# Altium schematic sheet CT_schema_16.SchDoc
size 389 x 385 mm
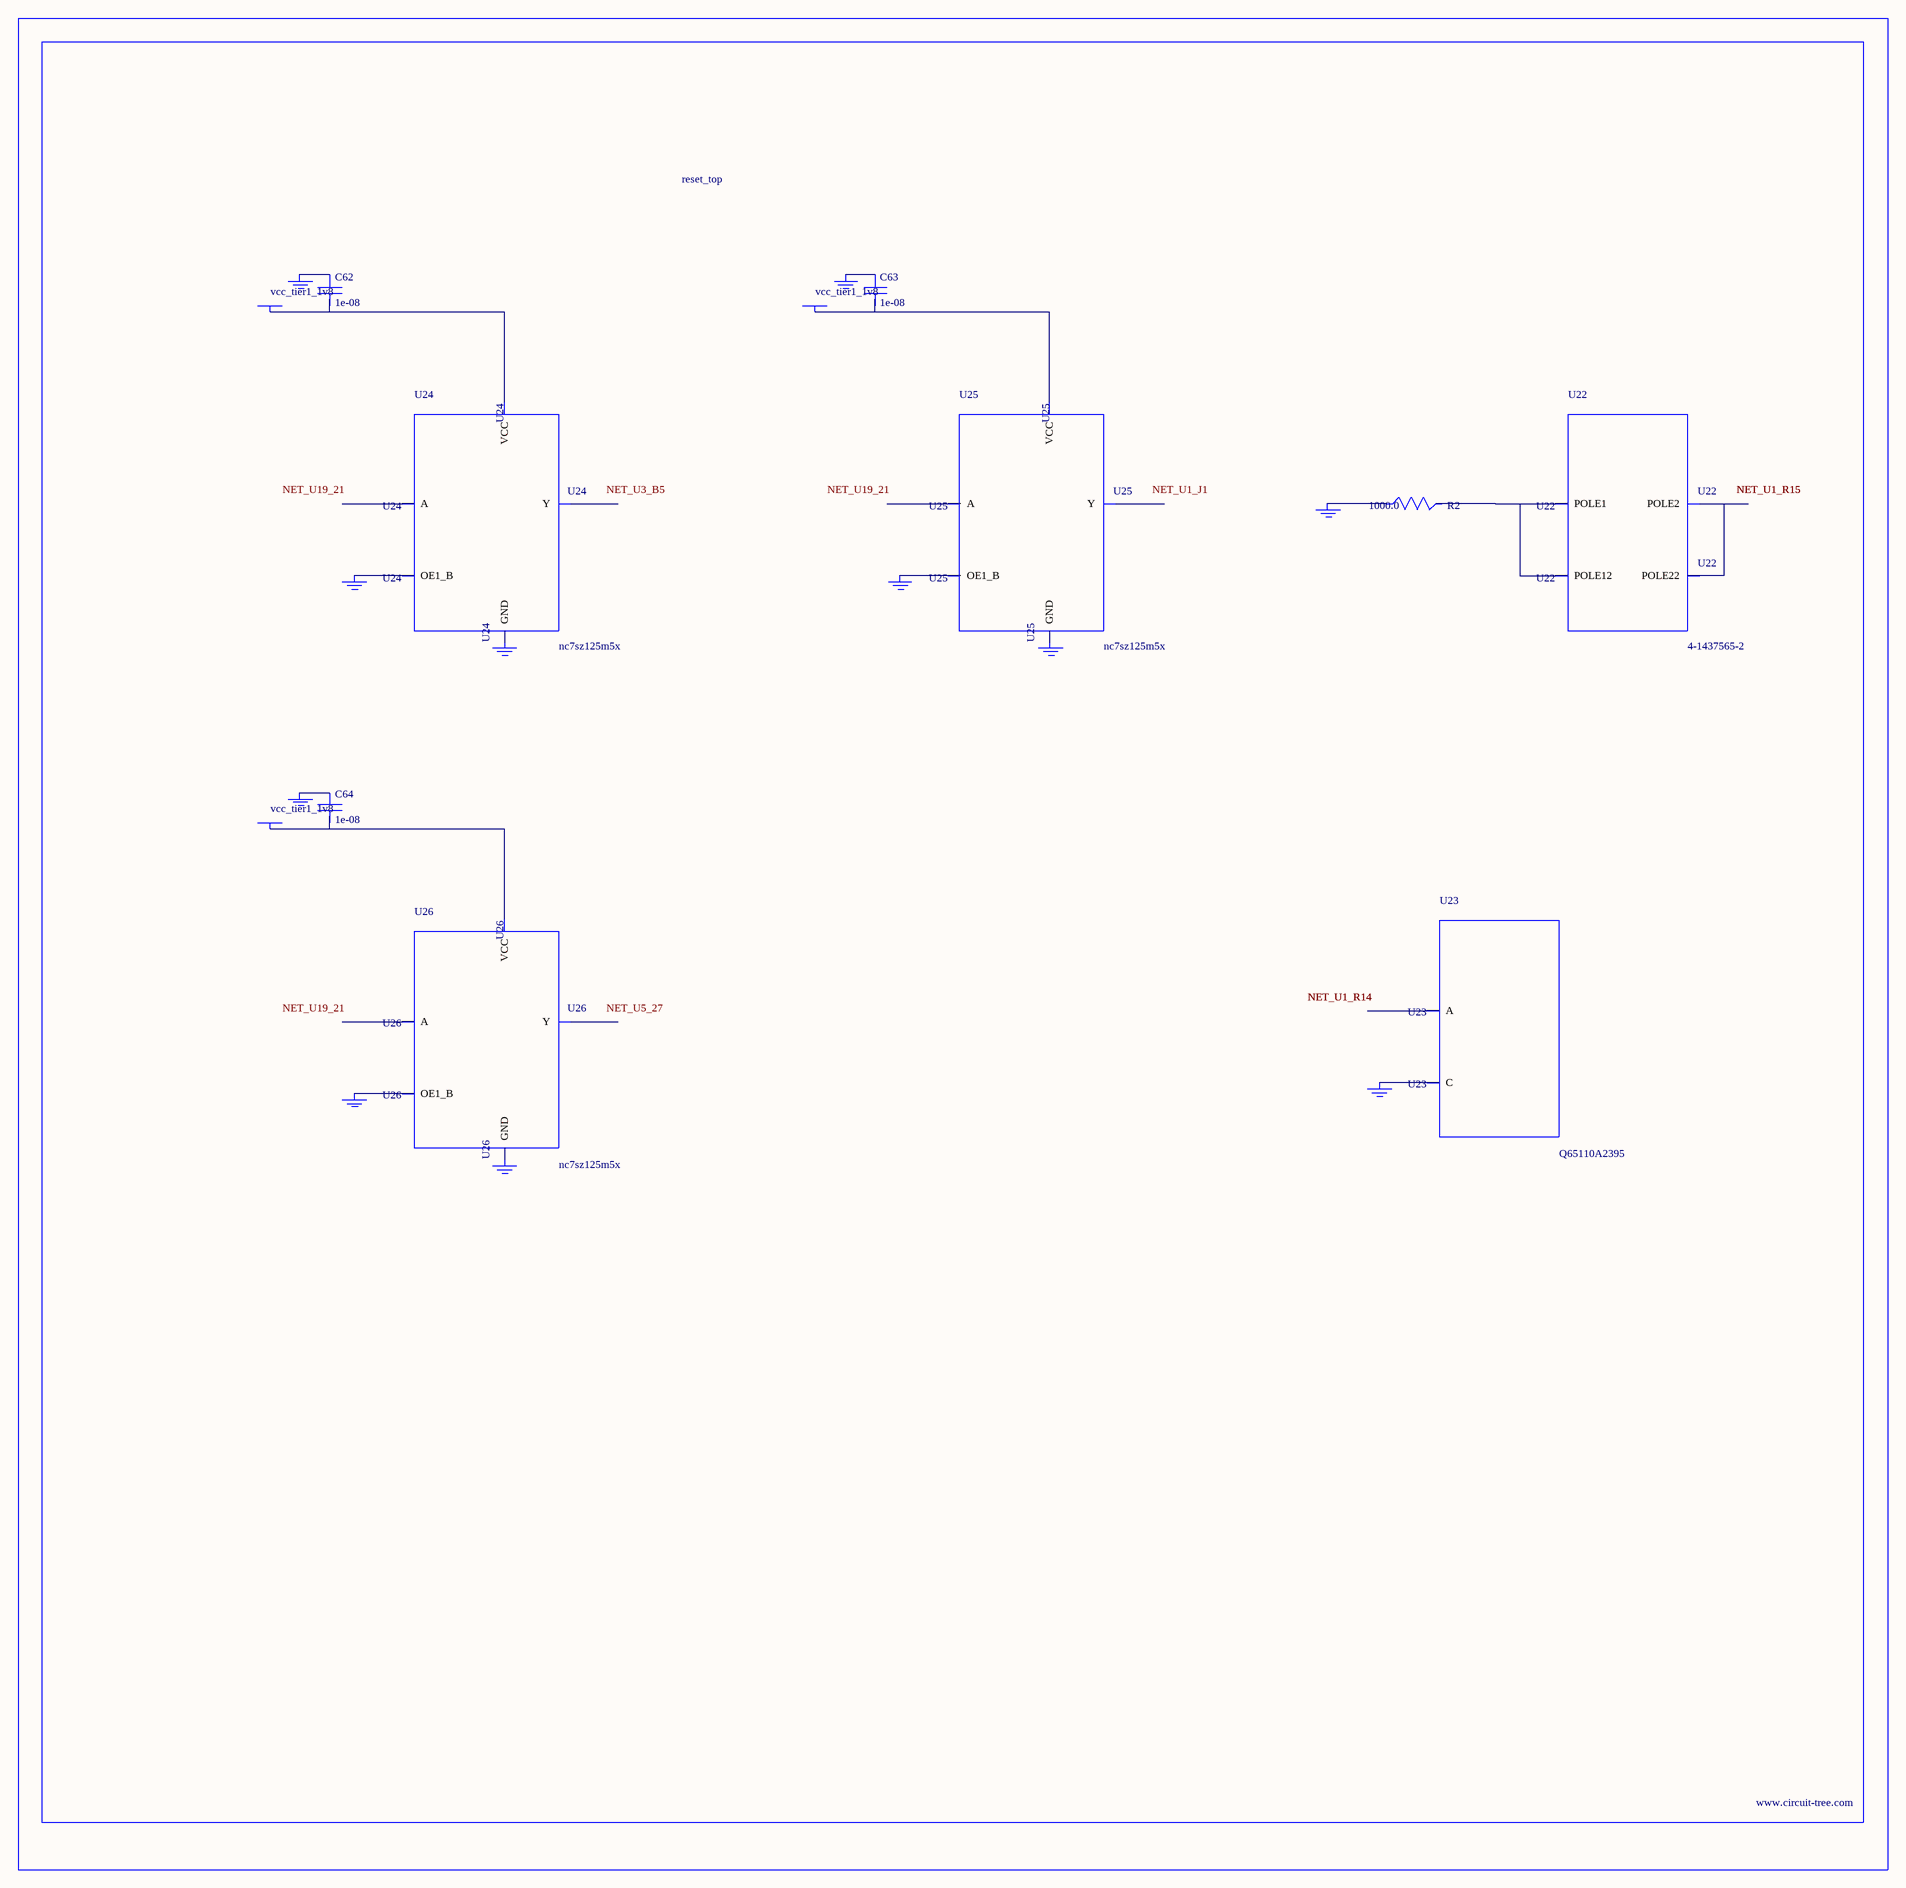
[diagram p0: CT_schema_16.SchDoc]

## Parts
BORDER15  (no value)
C62  1e-08  [C0402]
C63  1e-08  [C0402]
C64  1e-08  [C0402]
GND_INSTANCE_15_0  (no value)
GND_INSTANCE_15_1  (no value)
GND_INSTANCE_15_2  (no value)
GND_INSTANCE_15_3  (no value)
GND_INSTANCE_15_4  (no value)
GND_INSTANCE_15_5  (no value)
GND_INSTANCE_15_6  (no value)
GND_INSTANCE_15_7  (no value)
GND_INSTANCE_15_8  (no value)
GND_INSTANCE_15_9  (no value)
GND_INSTANCE_15_10  (no value)
POWER_INSTANCE_15_0  vcc_tier1_1v8
POWER_INSTANCE_15_1  vcc_tier1_1v8
POWER_INSTANCE_15_2  vcc_tier1_1v8
R2  1000.0  [R0603]
U22  4-1437565-2  [SW_4-1437565-2]
U23  Q65110A2395  [LGM67K-G1J2-24-Z]
U24  nc7sz125m5x  [NC7SZ125M5X]
U25  nc7sz125m5x  [NC7SZ125M5X]
U26  nc7sz125m5x  [NC7SZ125M5X]

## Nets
NetC62_1: C62.1 GND_INSTANCE_15_2.0(GND)
NetC62_2: C62.2 POWER_INSTANCE_15_0.0(PWR) U24.5(VCC)
NetC63_1: C63.1 GND_INSTANCE_15_5.0(GND)
NetC63_2: C63.2 POWER_INSTANCE_15_1.0(PWR) U25.5(VCC)
NetC64_1: C64.1 GND_INSTANCE_15_8.0(GND)
NetC64_2: C64.2 POWER_INSTANCE_15_2.0(PWR) U26.5(VCC)
NetGND_INSTANCE_15_0_0: GND_INSTANCE_15_0.0(GND) R2.1
NetGND_INSTANCE_15_1_0: GND_INSTANCE_15_1.0(GND) U23.C
NetGND_INSTANCE_15_3_0: GND_INSTANCE_15_3.0(GND) U24.1(OE1_B)
NetGND_INSTANCE_15_4_0: GND_INSTANCE_15_4.0(GND) U24.3(GND)
NetGND_INSTANCE_15_6_0: GND_INSTANCE_15_6.0(GND) U25.1(OE1_B)
NetGND_INSTANCE_15_7_0: GND_INSTANCE_15_7.0(GND) U25.3(GND)
NetGND_INSTANCE_15_9_0: GND_INSTANCE_15_9.0(GND) U26.1(OE1_B)
NetGND_INSTANCE_15_10_0: GND_INSTANCE_15_10.0(GND) U26.3(GND)
NetR2_2: R2.2 U22.1(POLE1) U22.2(POLE12)
NetU22_3: U22.3(POLE2) U22.4(POLE22)

Not connected (* = marked no-connect by the designer): U23 A; U24 2(A) 4(Y); U25 2(A) 4(Y); U26 2(A) 4(Y)

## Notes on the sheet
- Labels drawn without touching a wire or pin: NET_U1_J1, NET_U3_B5, NET_U5_27, NET_U19_21

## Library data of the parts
BORDER15 = BORDER_PAGE15
C62-C64 = C0402C103K3RAC
GND_INSTANCE_15_0-GND_INSTANCE_15_10 = GND
POWER_INSTANCE_15_0-POWER_INSTANCE_15_2 = PWR
R2 = RC0603JR-071KL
